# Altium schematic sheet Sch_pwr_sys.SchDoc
size Letter
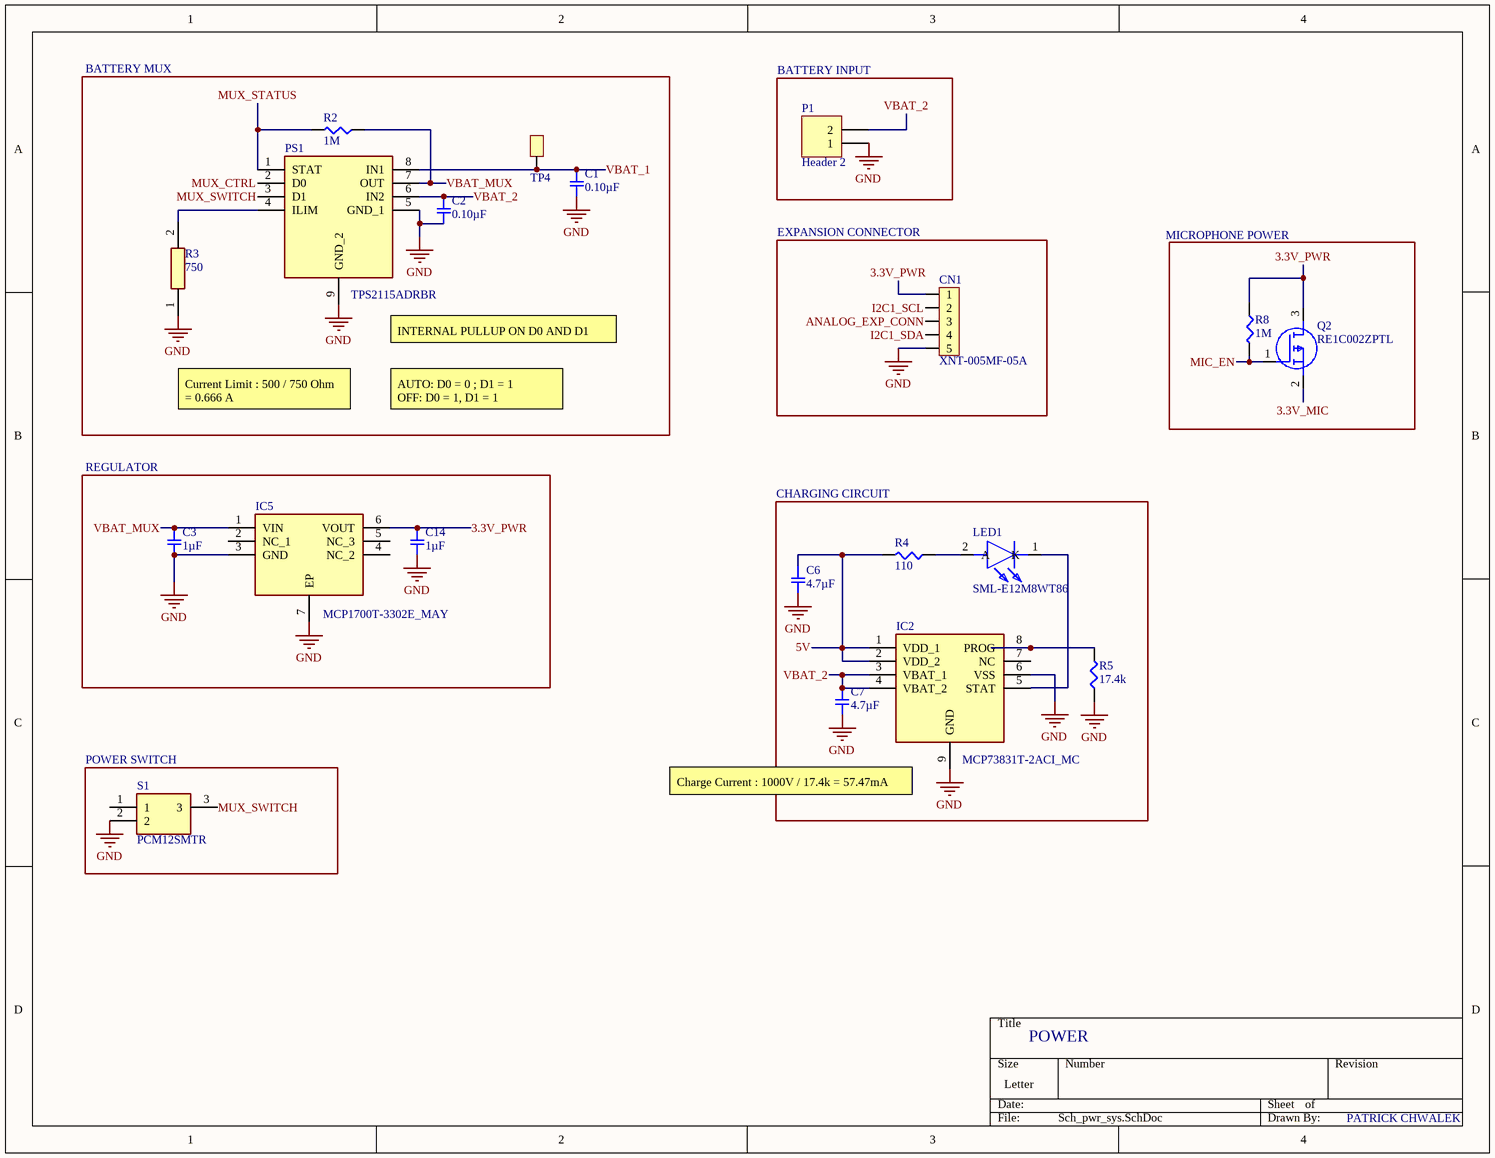
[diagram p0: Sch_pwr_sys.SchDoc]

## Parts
C1  0.10µF  [SMD-0402C]
C2  0.10µF  [SMD-0402C]
C3  1µF  [SMD-0402C]
C6  4.7µF  [SMD-0402C]
C7  4.7µF  [SMD-0402C]
C14  1µF  [SMD-0402C]
CN1  XNT-005MF-05A  [XNT-005MF-05A]
IC2  MCP73831T-2ACI_MC  [SON50P300X200X100-9N-D]
IC5  MCP1700T-3302E_MAY  [SON65P200X200X90-7N]
LED1  SML-E12M8WT86  [LEDC1608X46N]
P1  Header 2  [HDR1X2]
PS1  TPS2115ADRBR  [SON65P300X300X100-9N-D]
Q2  RE1C002ZPTL  [SOTFL50P160X85-3N]
R2  1M  [SMD-0402-RES]
R3  750  [RESC1005X40N]
R4  110  [SMD-0402-RES]
R5  17.4k  [SMD-0402-RES]
R8  1M  [SMD-0402-RES]
S1  PCM12SMTR  [PCM12SMTR_1]
TP4  TestPoint  [TestPoint_0.4mm]  (value not drawn)

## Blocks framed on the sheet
BATTERY MUX: C1 C2 PS1 R2 R3 TP4
BATTERY INPUT: P1
EXPANSION CONNECTOR: CN1
REGULATOR: C3 C14 IC5
CHARGING CIRCUIT: C6 C7 IC2 LED1 R4 R5
POWER SWITCH: S1

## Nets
GND: C1.2 C2.2 C3.2 C6.2 C7.2 C14.2 CN1.5 IC2.6(VSS) IC2.9(GND) IC5.3(GND) IC5.7(EP) P1.1 PS1.5(GND_1) PS1.9(GND_2) R3.1 R5.1 S1.2
3.3V_MIC: Q2.2(S)
3.3V_PWR: C14.1 CN1.1 IC5.6(VOUT) Q2.3(D) R8.1
5V: C6.1 IC2.1(VDD_1) IC2.2(VDD_2) R4.2
ANALOG_EXP_CONN: CN1.3
I2C1_SCL: CN1.2
I2C1_SDA: CN1.4
MIC_EN: Q2.1(G) R8.2
MUX_CTRL: PS1.2(D0)
MUX_STATUS: PS1.1(STAT) R2.2
MUX_SWITCH: PS1.3(D1) S1.3
VBAT_1: C1.1 PS1.8(IN1) TP4.1
VBAT_2: C2.1 C7.1 IC2.3(VBAT_1) IC2.4(VBAT_2) P1.2 PS1.6(IN2)
VBAT_MUX: C3.1 IC5.1(VIN) PS1.7(OUT) R2.1
NetIC2_5: IC2.5(STAT) LED1.1(K)
NetIC2_8: IC2.8(PROG) R5.2
NetLED1_2: LED1.2(A) R4.1
NetPS1_4: PS1.4(ILIM) R3.2

Not connected (* = marked no-connect by the designer): IC2 7(NC); IC5 2(NC_1) 4(NC_2) 5(NC_3); S1 1

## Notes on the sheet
- MICROPHONE POWER
- (near PS1) INTERNAL PULLUP ON D0 AND D1
- Current Limit : 500 / 750 Ohm = 0.666 A
- AUTO: D0 = 0 ; D1 = 1
  OFF: D0 = 1, D1 = 1
- (near IC2) Charge Current : 1000V / 17.4k = 57.47mA
- POWER
- PATRICK CHWALEK

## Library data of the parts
C1 C2 = GCM155R71C104KA55D: CAP CER 0.1UF 16V X7R 0402; Manufacturer: Murata Electronics North America; Factory Stock: 0; Unit Price (USD): 0.1; Minimum Quantity: 1; Tolerance: ±10%
C3 C14 = GCM155C71A105KE38D: CAP CER 1UF 10V X7S 0402; Manufacturer: Murata Electronics North America; Factory Stock: 0; Unit Price (USD): 0.12; Minimum Quantity: 1; Tolerance: ±10%
C6 C7 = GRM153R60G475ME15D: CAP CER 4.7UF 4V X5R 0402; Manufacturer: Murata Electronics North America; Factory Stock: 0; Unit Price (USD): 0.27; Minimum Quantity: 1; Tolerance: ±20%
IC2 = MCP73831T-2ACI_MC: Integrated Circuit; Manufacturer_Name: Microchip; Manufacturer_Part_Number: MCP73831T-2ACI/MC; Allied_Number: 70452042
IC5 = MCP1700T-3302E_MAY: Integrated Circuit; Manufacturer_Name: Microchip; Manufacturer_Part_Number: MCP1700T-3302E/MAY; Allied_Number: 70567878
LED1 = SML-E12M8WT86: LED; Manufacturer_Name: ROHM Semiconductor
P1 = Header 2: Header, 2-Pin
PS1 = TPS2115ADRBR: Power Supply; Manufacturer_Name: Texas Instruments
Q2 = RE1C002ZPTL: MOSFET (P-Channel); Manufacturer_Name: ROHM Semiconductor
R2 R8 = ERJ-2GEJ105X: RES SMD 1M OHM 5% 1/10W 0402; Manufacturer: Panasonic Electronic Components; Factory Stock: 0; Unit Price (USD): 0.00350; @ qty: 1500; Minimum Quantity: 1; Power (Watts): 0.1W, 1/10W; Temperature Coefficient: ±200ppm/°C
R3 = ERJ-2RKF7500X: RES SMD 750 OHM 1% 1/10W 0402; Manufacturer_Name: Panasonic; Allied_Number: 70265602
R4 = ERJ-2RKF8062X: RES SMD 110 OHM 5% 1/10W 0402; Manufacturer: Panasonic Electronic Components; Factory Stock: 0; Unit Price (USD): 0.00496; @ qty: 1500; Minimum Quantity: 1; Power (Watts): 0.1W, 1/10W; Temperature Coefficient: ±100ppm/°C
R5 = ERJ-2GEJ103X: RES SMD 17.4K OHM 1% 1/10W 0402; Manufacturer: Panasonic Electronic Components; Factory Stock: 0; Unit Price (USD): 0.00350; @ qty: 1500; Minimum Quantity: 1; Power (Watts): 0.1W, 1/10W; Temperature Coefficient: ±200ppm/°C
S1 = PCM12SMTR: Switch; Manufacturer_Name: C & K COMPONENTS; Allied_Number: 70417448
